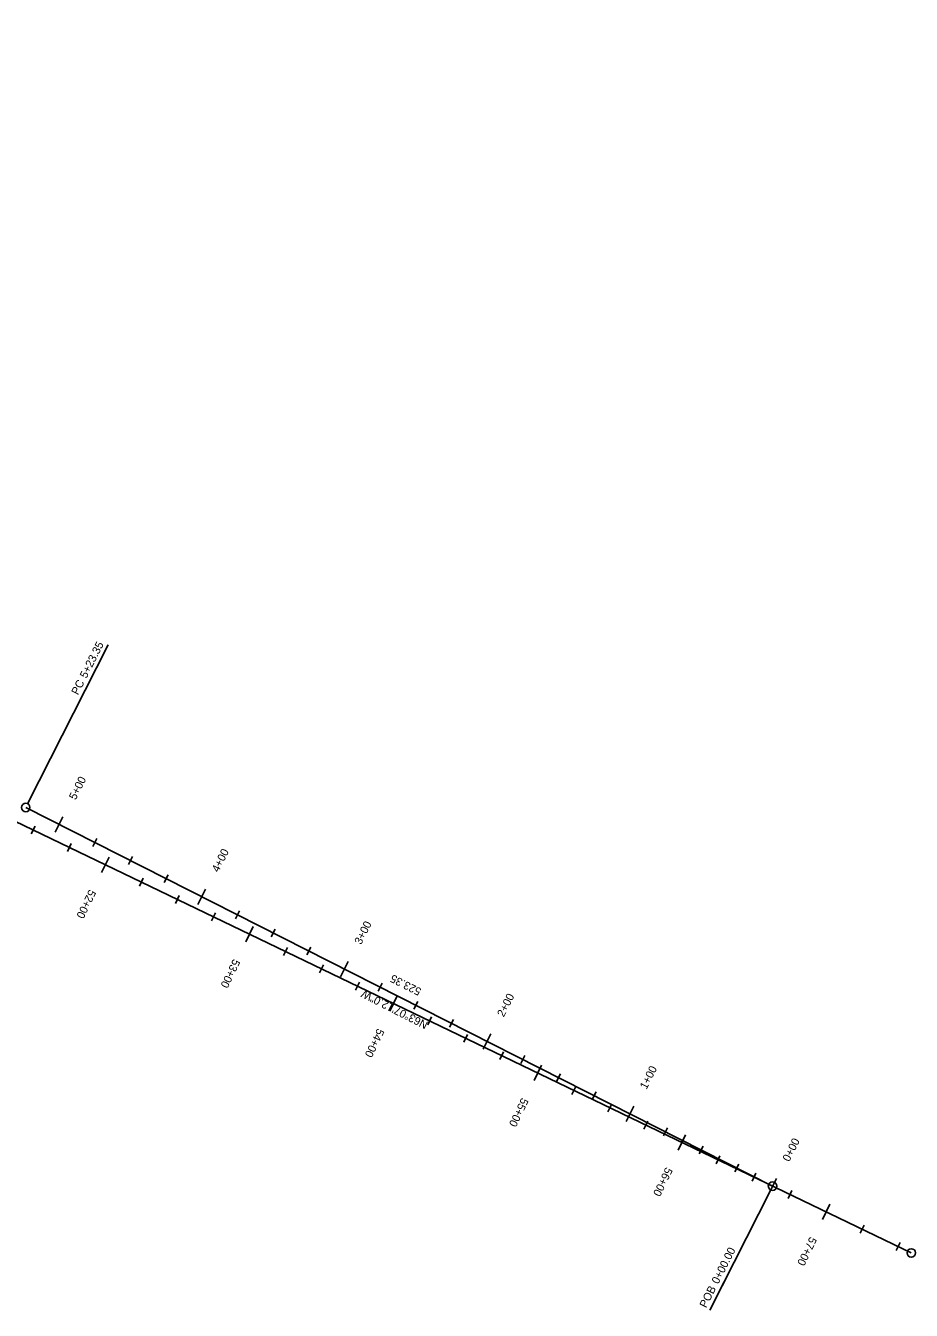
# Model space of a CAD drawing. Extents: x 2300830 to 2307917, y 756066 to 766359.
# Drawn here: x 2304965 to 2305519, y 761107 to 761909 of the extents above; entities that cross this region are included whole.
import ezdxf

# ---------------------------------------------------------------- set-up
doc = ezdxf.new("R2010")
doc.units = 0
for name, color, linetype in [('Default', 7, 'Continuous'), ('Draft_Bearing Label', 7, 'Continuous'), ('Draft_Station Cardinal Lines', 7, 'Continuous'), ('Draft_Station Cardinal Points', 7, 'Continuous'), ('Draft_Station Labels Major', 7, 'Continuous'), ('Draft_Station Ticks Major', 7, 'Continuous'), ('Draft_Station Ticks Minor', 7, 'Continuous'), ('Geom_Baseline', 7, 'Continuous')]:
    doc.layers.add(name, color=color, linetype=linetype)

msp = doc.modelspace()

# ---------------------------------------------------------------- linework, layer by layer
at = {"layer": 'Default'}
for p, q in [((2303926.45, 761909.44), (2305518.87, 761142.43)), ((2305432.18, 761184.18), (2304965.38, 761420.8))]:
    msp.add_line(p, q, dxfattribs=at)
at = {"layer": 'Draft_Station Cardinal Lines'}
msp.add_line((2304966.58, 761423.18), (2305016.92, 761522.49), dxfattribs=at)
at = {"layer": 'Draft_Station Cardinal Points'}
for p, q in [((2305016.92, 761522.49), (2305016.92, 761522.49)), ((2305430.97, 761181.8), (2305392.85, 761106.58)), ((2305432.18, 761184.18), (2305432.18, 761184.18)), ((2305392.85, 761106.58), (2305401.75, 761124.14))]:
    msp.add_line(p, q, dxfattribs=at)
for centre in [(2304965.38, 761420.8), (2305432.18, 761184.18), (2305518.87, 761142.43)]:
    msp.add_circle(centre, 2.67, dxfattribs=at)
at = {"layer": 'Draft_Station Ticks Major'}
for p, q in [((2304983.79, 761405.48), (2304988.59, 761414.96)), ((2305017.45, 761389.87), (2305012.84, 761380.3)), ((2305072.99, 761360.27), (2305077.79, 761369.74)), ((2305107.54, 761346.48), (2305102.94, 761336.91)), ((2305162.18, 761315.06), (2305166.98, 761324.53)), ((2305197.64, 761303.08), (2305193.03, 761293.51)), ((2305251.38, 761269.85), (2305256.18, 761279.32)), ((2305287.73, 761259.69), (2305283.12, 761250.12)), ((2305340.57, 761224.63), (2305345.37, 761234.11)), ((2305377.83, 761216.29), (2305373.22, 761206.72)), ((2305429.77, 761179.42), (2305434.57, 761188.89)), ((2305467.92, 761172.9), (2305463.31, 761163.33))]:
    msp.add_line(p, q, dxfattribs=at)
at = {"layer": 'Draft_Station Ticks Minor'}
for p, q in [((2304971.28, 761409.24), (2304968.89, 761404.27)), ((2304993.81, 761398.4), (2304991.41, 761393.42)), ((2305007.26, 761396.48), (2305009.75, 761401.4)), ((2305029.55, 761385.18), (2305032.05, 761390.1)), ((2305051.85, 761373.87), (2305054.35, 761378.8)), ((2305038.85, 761376.7), (2305036.46, 761371.73)), ((2305061.38, 761365.85), (2305058.98, 761360.88)), ((2305083.9, 761355), (2305081.51, 761350.03)), ((2305096.45, 761351.27), (2305098.95, 761356.19)), ((2305118.75, 761339.97), (2305121.25, 761344.89)), ((2305128.95, 761333.3), (2305126.55, 761328.33)), ((2305141.05, 761328.66), (2305143.54, 761333.59)), ((2305151.47, 761322.46), (2305149.08, 761317.48)), ((2305173.99, 761311.61), (2305171.6, 761306.63)), ((2305185.65, 761306.06), (2305188.14, 761310.98)), ((2305207.95, 761294.75), (2305210.44, 761299.68)), ((2305219.04, 761289.91), (2305216.65, 761284.94)), ((2305230.24, 761283.45), (2305232.74, 761288.37)), ((2305241.56, 761279.06), (2305239.17, 761274.09)), ((2305264.09, 761268.21), (2305261.69, 761263.24)), ((2305274.84, 761260.84), (2305277.34, 761265.77)), ((2305297.14, 761249.54), (2305299.64, 761254.46)), ((2305309.14, 761246.51), (2305306.74, 761241.54)), ((2305319.44, 761238.24), (2305321.94, 761243.16)), ((2305331.66, 761235.67), (2305329.26, 761230.69)), ((2305354.18, 761224.82), (2305351.79, 761219.84)), ((2305364.04, 761215.63), (2305366.53, 761220.55)), ((2305386.34, 761204.33), (2305388.83, 761209.25)), ((2305399.23, 761203.12), (2305396.83, 761198.15)), ((2305408.64, 761193.03), (2305411.13, 761197.95)), ((2305421.75, 761192.27), (2305419.36, 761187.3)), ((2305444.28, 761181.42), (2305441.88, 761176.45)), ((2305489.32, 761159.72), (2305486.93, 761154.75)), ((2305511.85, 761148.88), (2305509.45, 761143.9))]:
    msp.add_line(p, q, dxfattribs=at)
at = {"layer": 'Geom_Baseline'}
for p, q in [((2303926.45, 761909.44), (2305518.87, 761142.43)), ((2305432.18, 761184.18), (2304965.38, 761420.8))]:
    msp.add_line(p, q, dxfattribs=at)

# ---------------------------------------------------------------- texts
at = {"layer": 'Draft_Bearing Label'}
for s, p in [('523.35', (2305213.1, 761307.43)), ('N63°07\'12.0"W', (2305217.21, 761286.56))]:
    msp.add_text(s, height=5, rotation=153.12, dxfattribs=at).set_placement(p)
at = {"layer": 'Draft_Station Cardinal Points'}
for s, p in [('5+23.35', (2305003.33, 761501.17)), ('PC', (2304998.06, 761490.78)), ('0+00.00', (2305398.18, 761122.6)), ('POB ', (2305390.63, 761107.71))]:
    msp.add_text(s, height=5, rotation=63.12, dxfattribs=at).set_placement(p)
at = {"layer": 'Draft_Station Labels Major'}
for s, rotation, p in [('5+00', 63.12, (2304996.57, 761425.17)), ('4+00', 63.12, (2305085.77, 761379.96)), ('52+00', 244.28167, (2305005.07, 761369.93)), ('3+00', 63.12, (2305174.96, 761334.75)), ('53+00', 244.28167, (2305095.16, 761326.53)), ('2+00', 63.12, (2305264.16, 761289.53)), ('54+00', 244.28167, (2305185.26, 761283.14)), ('1+00', 63.12, (2305353.35, 761244.32)), ('55+00', 244.28167, (2305275.35, 761239.74)), ('0+00', 63.12, (2305442.55, 761199.11)), ('56+00', 244.28167, (2305365.44, 761196.35)), ('57+00', 244.28167, (2305455.54, 761152.95))]:
    msp.add_text(s, height=5, rotation=rotation, dxfattribs=at).set_placement(p)

doc.saveas('drawing.dxf')
